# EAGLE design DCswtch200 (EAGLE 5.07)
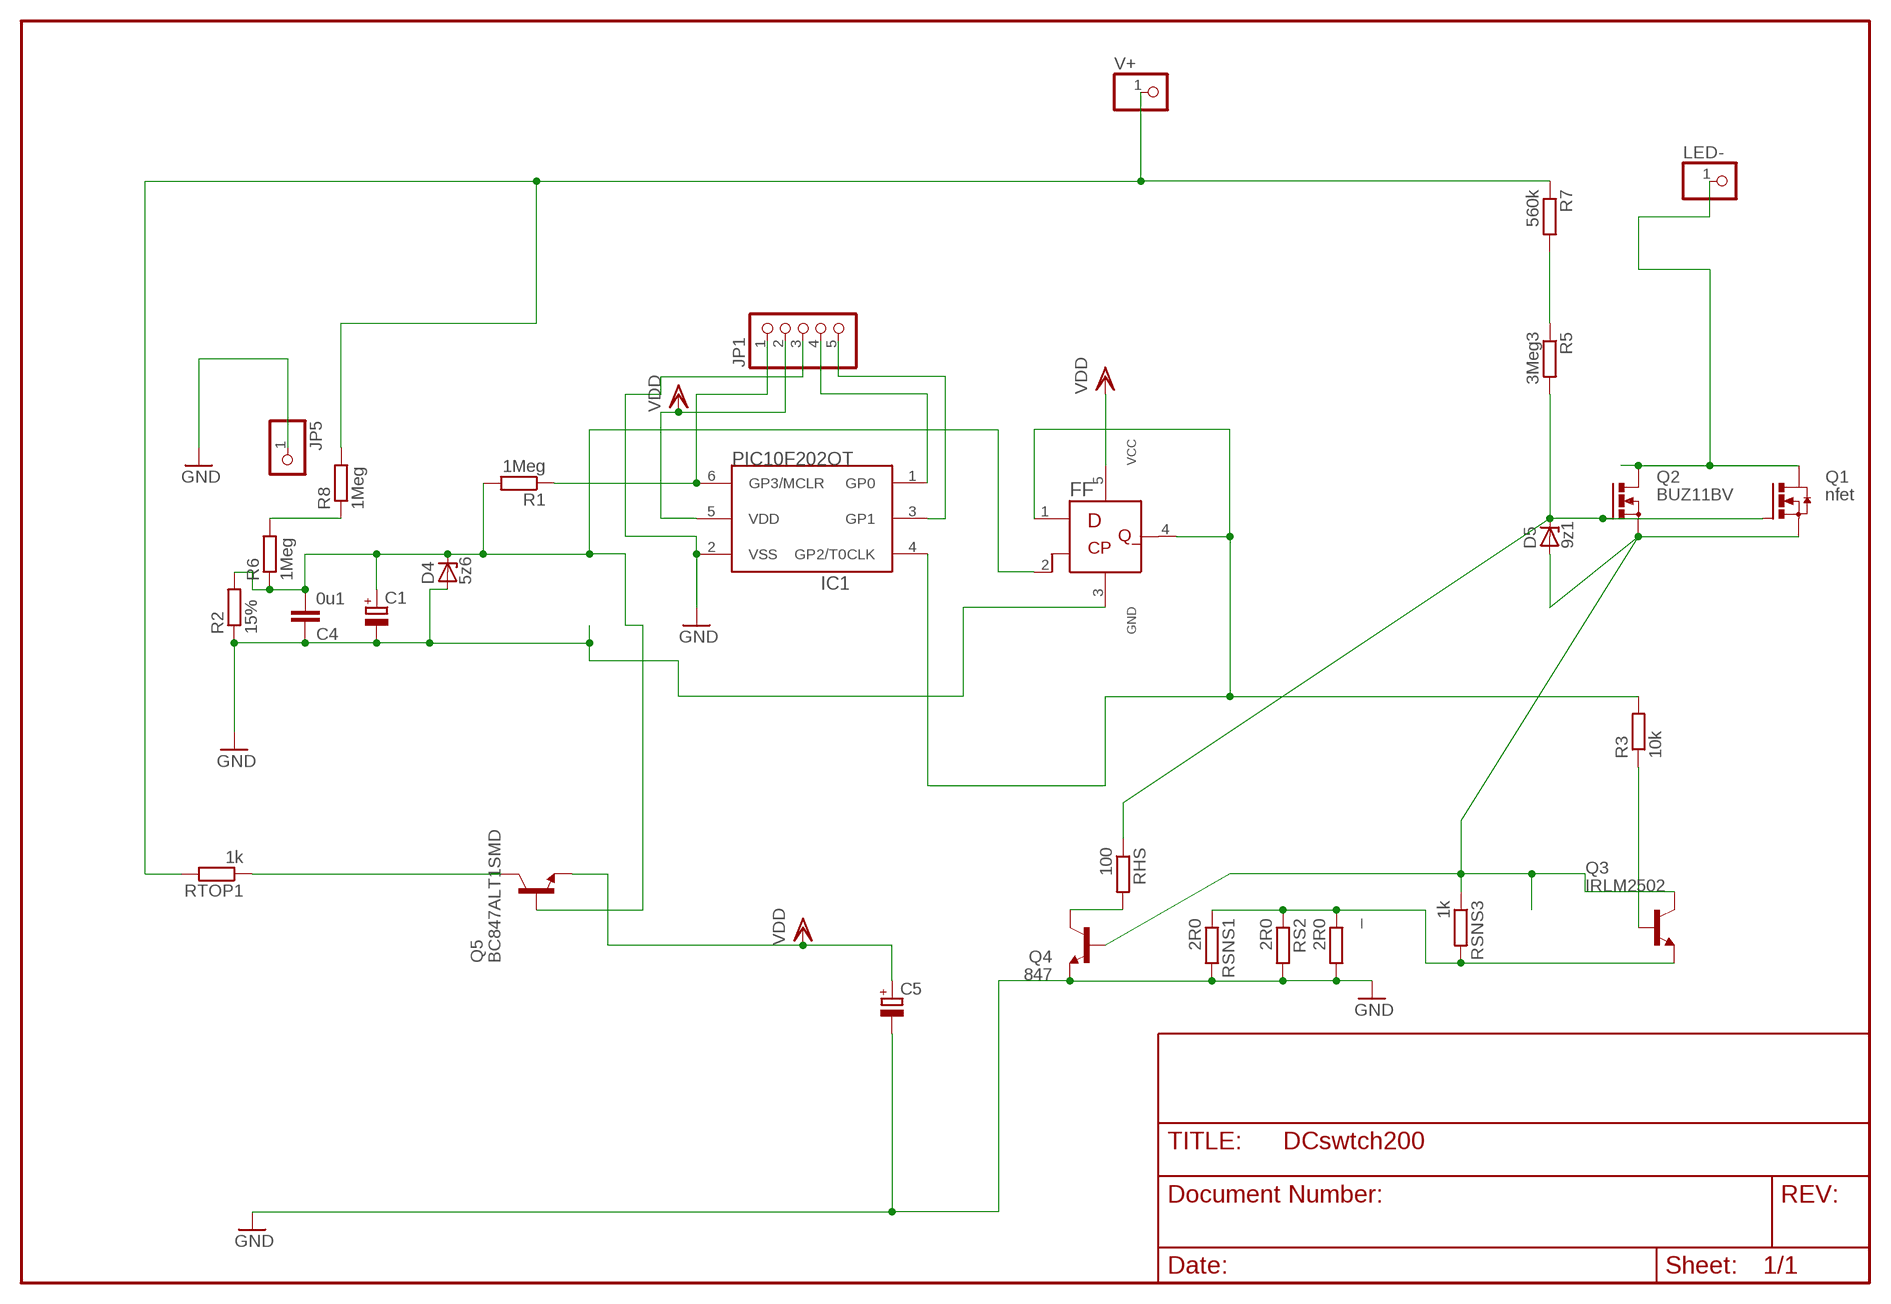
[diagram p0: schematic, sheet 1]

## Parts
_  2R0  R-EU_R2010  [R2010]
C1  CPOL-EUSMCA  [SMC_A]
C4  0u1  C-EUC1206  [C1206]
C5  CPOL-EUSANYO_SMD_C6  [SANYO-OSCON_SMD_C6]
D4  5z6  ZENER-DIODESOD80C  [SOD80C]
D5  9z1  ZENER-DIODESOD80C  [SOD80C]
FF  7479SOT23  [SOT23-5]
IC1  PIC10F202OT  [SOT23-6]
JP1  PINHD-1X5/90  [1X05/90]
JP5  PINHD-1X11MM6  [1X1MM8]
LED-  PINHD-1X11MM6  [1X1MM8]
Q1  nfet  N-HEXFET_DPAK-  [TO252]
Q2  BUZ11BV  [TO220BV]
Q3  IRLM2502  BC847ALT1SMD  [SOT23]
Q4  847  BC847ASMD  [SOT23]
Q5  BC847ALT1SMD  [SOT23]
R1  1Meg  R-EU_R0805  [R0805]
R2  15%  R-EU_R0805  [R0805]
R3  10k  R-EU_R0805  [R0805]
R5  3Meg3  R-EU_R1206  [R1206]
R6  1Meg  R-EU_R1206  [R1206]
R7  560k  R-EU_R1206  [R1206]
R8  1Meg  R-EU_R1206  [R1206]
RHS  100  R-EU_0204/5  [0204/5]
RS2  2R0  R-EU_R1206  [R1206]
RSNS1  2R0  R-EU_R2512  [R2512]
RSNS3  1k  R-EU_R1206  [R1206]
RTOP1  1k  R-EU_R1206  [R1206]
V+  PINHD-1X11MM6  [1X1MM8]

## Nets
BSW1: _.1 Q3.2(E) RS2.1 RSNS1.1 RSNS3.2
C: Q5.3(C) RTOP1.1
CB: C1.+ C4.2 D4.C FF.2(CP) Q5.1(B) R1.2 R2.2 R6.1
GND: _.2 C1.- C4.1 C5.- D4.A FF.3(GND) IC1.2(VSS) JP1.3 JP5.1 Q4.2(E) R2.1 RS2.2 RSNS1.2
LED-: LED-.1 Q1.3(D) Q2.D
N$1: D5.C Q1.1(G) Q2.G R5.2 RHS.1
N$2: FF.1(D) FF.4(Q_) IC1.4(GP2/T0CLK) R3.2
N$3: IC1.6(GP3/MCLR) JP1.1 R1.1
N$4: R5.1 R7.2
N$5: Q3.1(B) R3.1
N$7: Q4.3(C) RHS.2
N$9: R6.2 R8.1
N$10: IC1.1(GP0) JP1.4
N$12: IC1.3(GP1) JP1.5
S: D5.A Q1.2(S) Q2.S Q3.3(C) Q4.1(B) RSNS3.1
VDD: C5.+ FF.5(VCC) IC1.5(VDD) JP1.2 Q5.2(E)
VPLUS: R7.1 R8.2 RTOP1.2 V+.1

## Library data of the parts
_ R3 R5 R7 RHS RS2 RSNS1 RSNS3 RTOP1 = rcl:R-EU_: RESISTOR, European symbol
C1 = rcl:CPOL-EU: POLARIZED CAPACITOR, European symbol
C4 = rcl:C-EU: CAPACITOR, European symbol
C5 = rcl-2:CPOL-EU: POLARIZED CAPACITOR, European symbol
D4 D5 = diode:ZENER-DIODE: Z-Diode
FF = 74xx-little-de:7479
IC1 = microchip-5:PIC10F20*: uPC nW 0,25/0,5k Program Flash memory
JP1 = pinhead:PINHD-1X5: PIN HEADER
JP5 LED- V+ = pinhead:PINHD-1X1: PIN HEADER
Q1 = transistor-power:N-HEXFET_?-*: HEXFET® Power MOSFET
Q2 = transistor-power:BUZ11: N-CHANNEL MOS FET
Q3-Q5 = transistor-npn:BC847*: NPN Transistor
R1 R2 R6 R8 = rcl-2:R-EU_: RESISTOR, European symbol

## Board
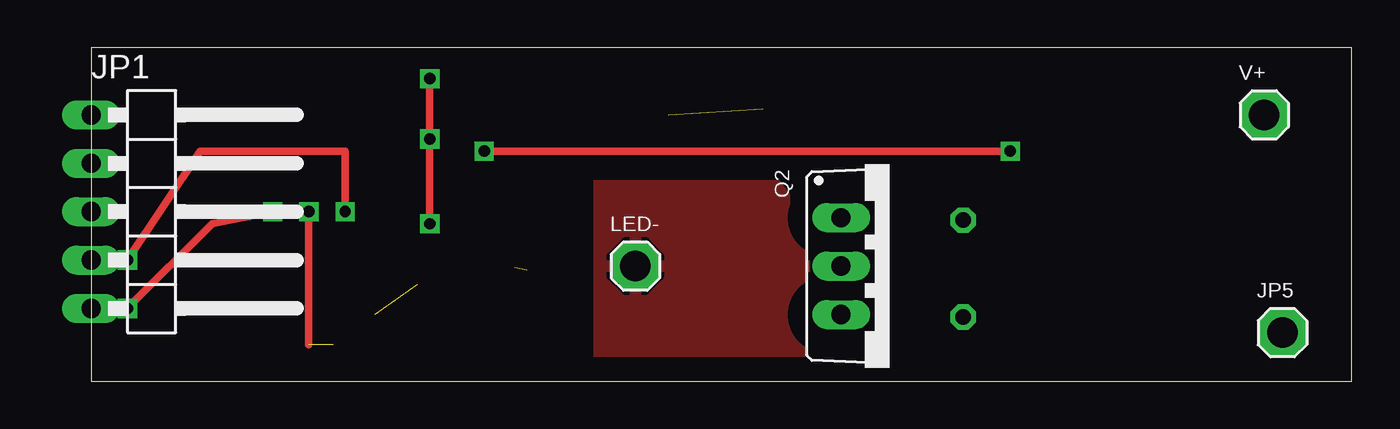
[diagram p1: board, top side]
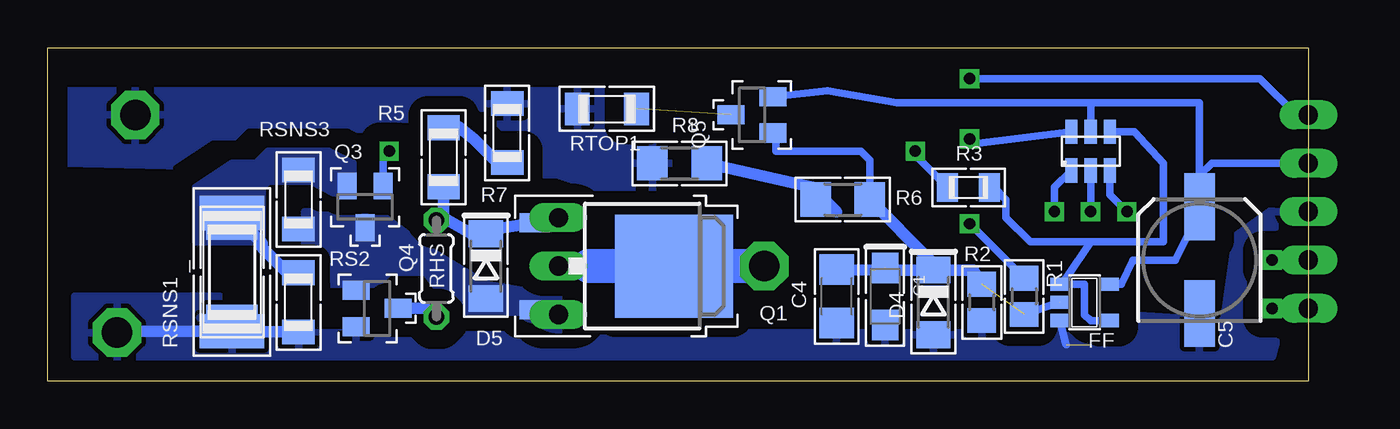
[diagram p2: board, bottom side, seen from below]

Size 66.2 x 17.5 mm. Coordinates in mm from the lower left corner, seen from the top.
Outline: 0,0 66.2,0 66.2,17.5 0,17.5 0,0
Copper layers (1*16): Top 0.035mm / dielectric 1.5mm / Bottom 0.035mm
Design rules "default *": minimum track width 10mil, minimum drill 24mil, track to track 8mil, track to pad 8mil, pad to pad 8mil, via to via 8mil, smd to smd 8mil, copper to edge 20mil, drill to drill 8mil, minimum pad ring 10mil, minimum via ring 8mil, stop-mask expansion 4mil, vias tented up to drill 0mil, thermal gap 10mil

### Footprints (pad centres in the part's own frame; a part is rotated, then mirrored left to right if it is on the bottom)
R2010 = smd 1.4 x 2.7: 1 -2.4,0; 2 2.4,0
SMC_A = smd 1.6 x 1.4: + -1.5,0; - 1.5,0
C1206 = smd 1.6 x 1.8: 1 -1.4,0; 2 1.4,0
SANYO-OSCON_SMD_C6 = smd 3.5 x 1.6: + 2.8,0; - -2.8,0
SOD80C = smd 1.4 x 1.8: A 1.7,0; C -1.7,0
SOT23-5 = smd 0.69 x 0.99: 1 -0.95,-1.29; 2 0,-1.29; 3 0.95,-1.29; 4 0.95,1.3; 5 -0.95,1.3
SOT23-6 = smd 0.635 x 1.27: 1 -1.016,-1.016; 2 0,-1.016; 3 1.016,-1.016; 4 1.016,1.016; 5 0,1.016; 6 -1.016,1.016
1X05/90 = drill 1.016 long: 1 -5.08,-3.81; 2 -2.54,-3.81; 3 0,-3.81; 4 2.54,-3.81; 5 5.08,-3.81
1X1MM8 = drill 1.6 pad 2.54 octagon: 1 0,0
TO252 = smd 1 x 1.6: 1 -2.28,-3.53; 2 2.28,-3.53 | smd 5.4 x 6.2: 3 0,3.77
TO220BV = drill 1.016 long: D 0,-2.54; G -2.54,-2.54; S 2.54,-2.54
SOT23 = smd 1 x 1.4: 1 -0.95,-1.1; 2 0.95,-1.1; 3 0,1.1
R0805 = smd 1.3 x 1.5: 1 -0.95,0; 2 0.95,0
R0805' = smd 1.1 x 1.5: 1 -1.1,0; 2 1.1,0
R1206 = smd 1.3 x 1.7: 1 -1.55,0; 2 1.55,0
R1206' = smd 1.6 x 1.803: 1 -1.422,0; 2 1.422,0
0204/5 = drill 0.813 octagon: 1 -2.54,0; 2 2.54,0
R2512 = smd 1.8 x 3.4: 1 -3.1,0; 2 3.1,0

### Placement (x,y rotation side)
_  56.52,5.71 270 bottom
C1  22.22,4.45 270 bottom
C4  24.77,4.45 90 bottom
C5  5.71,6.35 90 bottom
D4  19.68,4.13 270 bottom
D5  43.18,6.03 270 bottom
FF  11.75,4.13 270 bottom
IC1  11.43,12.06 0 bottom
JP1  3.81,8.89 270 top
JP5  62.55,2.54 0 top
LED-  28.57,6.03 0 top
Q1  37.08,6.03 270 bottom
Q2  41.91,6.03 270 top
Q3  49.53,9.14 180 bottom
Q4  48.89,3.81 270 bottom
Q5  29.21,13.97 90 bottom
R1  14.92,4.45 270 bottom
R2  17.14,4.13 90 bottom
R3  10k  [R0805']  17.84,10.16 0 bottom
R5  45.4,11.75 270 bottom
R6  1Meg  [R1206']  24.45,9.53 180 bottom
R7  42.07,13.02 270 bottom
R8  1Meg  [R1206']  33.02,11.43 180 bottom
RHS  45.78,5.91 270 bottom
RS2  53.02,4.13 270 bottom
RSNS1  56.52,5.71 270 bottom
RSNS3  53.02,9.53 90 bottom
RTOP1  36.83,14.29 180 bottom
V+  61.59,13.97 0 top

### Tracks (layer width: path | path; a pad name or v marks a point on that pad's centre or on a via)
BSW1
  Bottom 0.61: RS2.1 53.62,5.68 54.93,6.99 54.93,7.23 RSNS1.1
  pour Bottom (isolate 0.813, rank 2, no thermals): 58.42,7.3 58.42,10.16 56.52,11.43 55.24,11.43 54.61,12.06 51.44,12.06 50.16,11.43 50.16,10.16 51.12,9.84 52.39,10.48 54.61,10.48 54.93,10.16 54.93,7.3
C  (1 unrouted)
CB  (2 unrouted)
  Bottom 0.406: R6.1 23.02,11.6 23.49,12.06 27.94,12.06 27.94,12.85 Q5.1 | R1.2 FF.2
  Bottom 0.61: R6.1 19.85,6.31 D4.C | D4.C 22.88,5.83 C4.2 | D4.C 17.58,5.83 R2.2
GND  (via drill 0.6)  (1 unrouted)
  Top 0.406: 11.43,1.91 v11.43,8.89
  Bottom 0.406: v11.43,8.89 IC1.2 | 12.7,1.91 12.72,1.93 FF.3
  Bottom 0.61: RSNS1.2 _.2 | RS2.2 56.52,2.58 RSNS1.2 | RSNS1.2 62.55,2.62 JP5.1
  pour Bottom (isolate 1.016): 57.15,4.45 64.77,4.45 64.77,1.27 1.91,1.27 -0.63,10.79 3.81,7.62 4.45,3.17 14.61,3.81 14.61,2.54 57.78,2.54
LED-
  Bottom 0.61: 37.78,6.03 Q2.D | Q1.3 28.07,5.59 LED-.1
  Bottom 1.778: LED-.1 37.78,6.03
  pour Top (isolate 1.27): 26.67,10.79 35.56,10.79 37.46,8.26 37.46,1.27 26.67,1.27
N$1
  Bottom 0.61: 45.4,8.57 R5.2 | 45.4,8.57 RHS.1 | Q2.G 39.91,8.57 Q1.1 43.43,7.87 D5.C 43.93,7.73 45.4,8.57
N$2
  Bottom 0.406: 11.43,7.3 12.7,5.42 FF.1 11.75,5.08 11.75,3.49 11.43,3.17 FF.4 | 11.43,7.3 7.62,7.3 7.62,11.43 9.14,13.08 IC1.4 | 11.43,7.3 14.61,7.3 15.88,8.57 15.88,9.53 16.51,10.16 R3.2
N$3  (via drill 0.6)
  Top 0.406: v17.78,8.26 v17.78,12.7 v17.78,15.88
  Bottom 0.406: JP1.1 0.64,13.97 2.54,15.88 v17.78,15.88 | v17.78,8.26 R1.1 | v17.78,12.7 17.53,12.45 IC1.6
N$4
  Bottom 0.61: R7.2 42.71,11.6 43.81,12.7 44.62,13.34 R5.1
N$5  (via drill 0.6)
  Top 0.406: v20.64,12.06 v48.26,12.06
  Bottom 0.406: R3.1 20.64,11.85 v20.64,12.06 | v48.26,12.06 48.58,11.74 Q3.1
N$7
  Bottom 0.61: Q4.3 46.35,3.81 RHS.2
N$9
  Bottom 0.61: R8.1 26.04,10.16 24.77,8.89 R6.2
N$10  (via drill 0.6)
  Top 0.406: v13.34,8.89 13.34,12.06 5.71,12.06 v1.91,6.35
  Bottom 0.406: IC1.1 13.34,10.16 v13.34,8.89 | JP1.4 v1.91,6.35
N$12  (via drill 0.6)
  Top 0.406: v1.91,3.81 6.35,8.26 v9.53,8.89
  Bottom 0.406: JP1.5 v1.91,3.81 | v9.53,8.89 10.41,9.78 IC1.3
S
  Bottom 0.61: Q1.2 39.55,3.31 Q2.S
  pour Bottom (isolate 0.813, rank 3, no thermals): 39.37,4.45 43.18,5.08 46.35,6.99 48.89,8.89 52.7,8.89 52.7,6.35 51.44,5.08 48.89,5.08 48.26,5.71 46.35,5.71 44.45,3.17 39.37,2.54
VDD
  Bottom 0.406: JP1.2 5.08,11.43 5.71,10.79 | 5.71,10.79 C5.+ 5.34,9.15 5.71,8.89 6.99,6.35 9.21,6.35 9.82,5.08 FF.5 | Q5.2 25.25,15.24 21.59,14.61 11.43,14.61 | 11.43,14.61 5.71,14.61 5.71,10.79 | 11.43,14.61 IC1.5
VPLUS
  pour Bottom (isolate 1.016, rank 3): 30.48,13.34 36.83,13.34 36.83,15.24 65.41,15.24 65.41,11.43 39.37,10.79 37.46,10.16 29.21,10.16 29.21,11.43 30.48,11.43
